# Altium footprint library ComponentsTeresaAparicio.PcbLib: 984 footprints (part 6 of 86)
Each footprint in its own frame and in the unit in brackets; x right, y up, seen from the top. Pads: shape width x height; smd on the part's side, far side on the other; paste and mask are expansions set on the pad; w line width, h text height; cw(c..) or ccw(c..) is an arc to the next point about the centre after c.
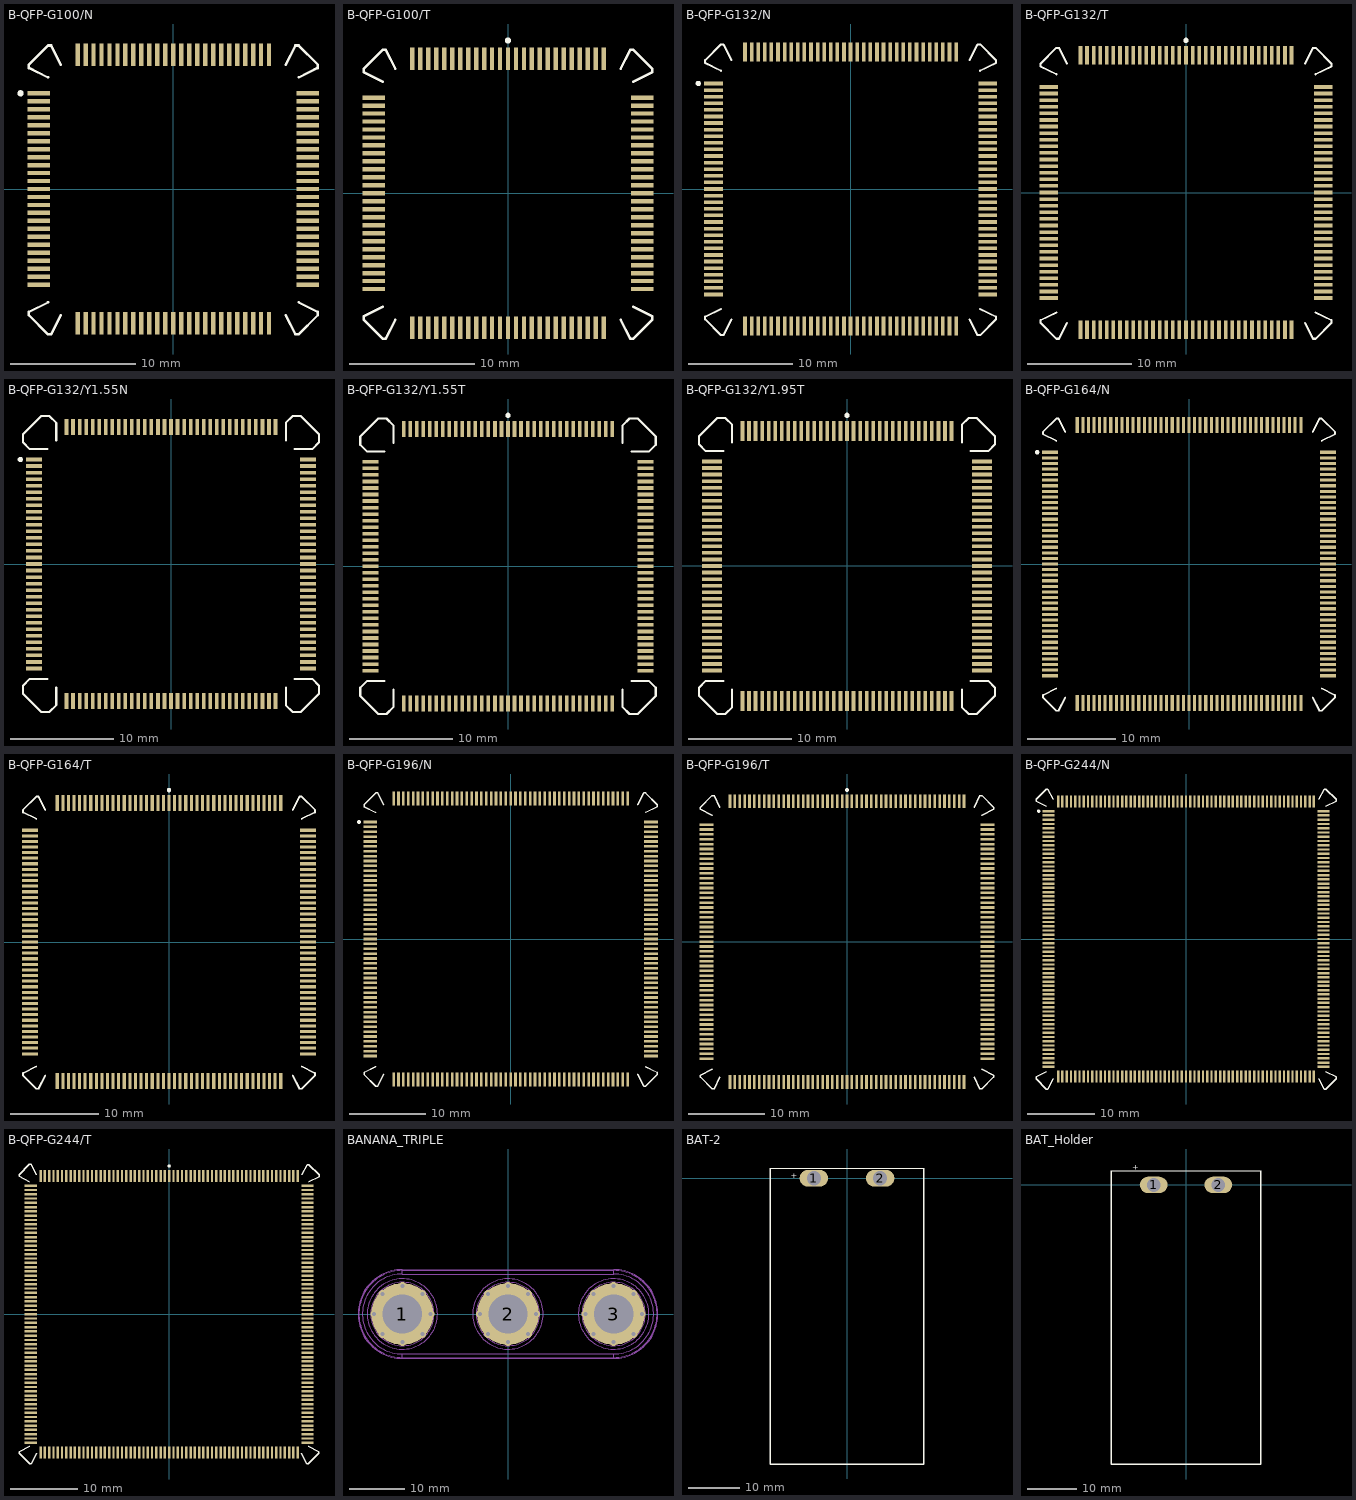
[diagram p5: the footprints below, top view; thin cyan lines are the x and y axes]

## B-QFP-G100/N [mm] "PQFP; 100 Leads; Body 19 x 19 mm; Pitch 0.635 mm"
height 4.57
pads (100):
  rect 1.8x0.35 smd: 1(-10.7,7.62) 2(-10.7,6.985) 3(-10.7,6.35) 4(-10.7,5.715) 5(-10.7,5.08) 6(-10.7,4.445) 7(-10.7,3.81) 8(-10.7,3.175) 9(-10.7,2.54) 10(-10.7,1.905) 11(-10.7,1.27) 12(-10.7,0.635) 13(-10.7,0) 14(-10.7,-0.635) 15(-10.7,-1.27) 16(-10.7,-1.905) 17(-10.7,-2.54) 18(-10.7,-3.175) 19(-10.7,-3.81) 20(-10.7,-4.445) 21(-10.7,-5.08) 22(-10.7,-5.715) 23(-10.7,-6.35) 24(-10.7,-6.985) 25(-10.7,-7.62) 51(10.7,-7.62) 52(10.7,-6.985) 53(10.7,-6.35) 54(10.7,-5.715) 55(10.7,-5.08) 56(10.7,-4.445) 57(10.7,-3.81) 58(10.7,-3.175) 59(10.7,-2.54) 60(10.7,-1.905) 61(10.7,-1.27) 62(10.7,-0.635) 63(10.7,0) 64(10.7,0.635) 65(10.7,1.27) 66(10.7,1.905) 67(10.7,2.54) 68(10.7,3.175) 69(10.7,3.81) 70(10.7,4.445) 71(10.7,5.08) 72(10.7,5.715) 73(10.7,6.35) 74(10.7,6.985) 75(10.7,7.62)
  rect 0.35x1.8 smd: 26(-7.62,-10.7) 27(-6.985,-10.7) 28(-6.35,-10.7) 29(-5.715,-10.7) 30(-5.08,-10.7) 31(-4.445,-10.7) 32(-3.81,-10.7) 33(-3.175,-10.7) 34(-2.54,-10.7) 35(-1.905,-10.7) 36(-1.27,-10.7) 37(-0.635,-10.7) 38(0,-10.7) 39(0.635,-10.7) 40(1.27,-10.7) 41(1.905,-10.7) 42(2.54,-10.7) 43(3.175,-10.7) 44(3.81,-10.7) 45(4.445,-10.7) 46(5.08,-10.7) 47(5.715,-10.7) 48(6.35,-10.7) 49(6.985,-10.7) 50(7.62,-10.7) 76(7.62,10.7) 77(6.985,10.7) 78(6.35,10.7) 79(5.715,10.7) 80(5.08,10.7) 81(4.445,10.7) 82(3.81,10.7) 83(3.175,10.7) 84(2.54,10.7) 85(1.905,10.7) 86(1.27,10.7) 87(0.635,10.7) 88(0,10.7) 89(-0.635,10.7) 90(-1.27,10.7) 91(-1.905,10.7) 92(-2.54,10.7) 93(-3.175,10.7) 94(-3.81,10.7) 95(-4.445,10.7) 96(-5.08,10.7) 97(-5.715,10.7) 98(-6.35,10.7) 99(-6.985,10.7) 100(-7.62,10.7)
Top Overlay:
  circle w0.25: c-12.16,7.62 r0.125
  lines w0.2: -11.5,-9.797 -9.976,-9.035 ; -11.5,-9.779 -11.5,-10.051 -9.976,-11.575 -9.722,-11.575 -8.96,-10.051 ; -11.5,9.629 -11.5,9.901 -9.976,11.425 -9.722,11.425 -8.96,9.901 ; -11.5,9.647 -9.976,8.885 ; 8.96,-10.051 9.722,-11.575 9.976,-11.575 11.5,-10.051 11.5,-9.779 ; 8.96,9.901 9.722,11.425 9.976,11.425 11.5,9.901 11.5,9.629 ; 9.976,-9.035 11.5,-9.797 ; 9.976,8.885 11.5,9.647

## B-QFP-G100/T [mm] "PQFP; 100 Leads; Body 19 x 19 mm; Pitch 0.635 mm"
height 4.57
pads (100):
  rect 0.35x1.8 smd: 1(0,10.7) 2(-0.635,10.7) 3(-1.27,10.7) 4(-1.905,10.7) 5(-2.54,10.7) 6(-3.175,10.7) 7(-3.81,10.7) 8(-4.445,10.7) 9(-5.08,10.7) 10(-5.715,10.7) 11(-6.35,10.7) 12(-6.985,10.7) 13(-7.62,10.7) 39(-7.62,-10.7) 40(-6.985,-10.7) 41(-6.35,-10.7) 42(-5.715,-10.7) 43(-5.08,-10.7) 44(-4.445,-10.7) 45(-3.81,-10.7) 46(-3.175,-10.7) 47(-2.54,-10.7) 48(-1.905,-10.7) 49(-1.27,-10.7) 50(-0.635,-10.7) 51(0,-10.7) 52(0.635,-10.7) 53(1.27,-10.7) 54(1.905,-10.7) 55(2.54,-10.7) 56(3.175,-10.7) 57(3.81,-10.7) 58(4.445,-10.7) 59(5.08,-10.7) 60(5.715,-10.7) 61(6.35,-10.7) 62(6.985,-10.7) 63(7.62,-10.7) 89(7.62,10.7) 90(6.985,10.7) 91(6.35,10.7) 92(5.715,10.7) 93(5.08,10.7) 94(4.445,10.7) 95(3.81,10.7) 96(3.175,10.7) 97(2.54,10.7) 98(1.905,10.7) 99(1.27,10.7) 100(0.635,10.7)
  rect 1.8x0.35 smd: 14(-10.7,7.62) 15(-10.7,6.985) 16(-10.7,6.35) 17(-10.7,5.715) 18(-10.7,5.08) 19(-10.7,4.445) 20(-10.7,3.81) 21(-10.7,3.175) 22(-10.7,2.54) 23(-10.7,1.905) 24(-10.7,1.27) 25(-10.7,0.635) 26(-10.7,0) 27(-10.7,-0.635) 28(-10.7,-1.27) 29(-10.7,-1.905) 30(-10.7,-2.54) 31(-10.7,-3.175) 32(-10.7,-3.81) 33(-10.7,-4.445) 34(-10.7,-5.08) 35(-10.7,-5.715) 36(-10.7,-6.35) 37(-10.7,-6.985) 38(-10.7,-7.62) 64(10.7,-7.62) 65(10.7,-6.985) 66(10.7,-6.35) 67(10.7,-5.715) 68(10.7,-5.08) 69(10.7,-4.445) 70(10.7,-3.81) 71(10.7,-3.175) 72(10.7,-2.54) 73(10.7,-1.905) 74(10.7,-1.27) 75(10.7,-0.635) 76(10.7,0) 77(10.7,0.635) 78(10.7,1.27) 79(10.7,1.905) 80(10.7,2.54) 81(10.7,3.175) 82(10.7,3.81) 83(10.7,4.445) 84(10.7,5.08) 85(10.7,5.715) 86(10.7,6.35) 87(10.7,6.985) 88(10.7,7.62)
Top Overlay:
  circle w0.25: c0,12.16 r0.125
  lines w0.2: -11.5,-9.797 -9.976,-9.035 ; -11.5,-9.779 -11.5,-10.051 -9.976,-11.575 -9.722,-11.575 -8.96,-10.051 ; -11.5,9.629 -11.5,9.901 -9.976,11.425 -9.722,11.425 -8.96,9.901 ; -11.5,9.647 -9.976,8.885 ; 8.96,-10.051 9.722,-11.575 9.976,-11.575 11.5,-10.051 11.5,-9.779 ; 8.96,9.901 9.722,11.425 9.976,11.425 11.5,9.901 11.5,9.629 ; 9.976,-9.035 11.5,-9.797 ; 9.976,8.885 11.5,9.647

## B-QFP-G132/N [mm] "PQFP; 132 Leads; Body 24 x 24 mm; Pitch 0.635 mm"
height 4.57
pads (132):
  rect 1.8x0.35 smd: 1(-13.2,10.16) 2(-13.2,9.525) 3(-13.2,8.89) 4(-13.2,8.255) 5(-13.2,7.62) 6(-13.2,6.985) 7(-13.2,6.35) 8(-13.2,5.715) 9(-13.2,5.08) 10(-13.2,4.445) 11(-13.2,3.81) 12(-13.2,3.175) 13(-13.2,2.54) 14(-13.2,1.905) 15(-13.2,1.27) 16(-13.2,0.635) 17(-13.2,0) 18(-13.2,-0.635) 19(-13.2,-1.27) 20(-13.2,-1.905) 21(-13.2,-2.54) 22(-13.2,-3.175) 23(-13.2,-3.81) 24(-13.2,-4.445) 25(-13.2,-5.08) 26(-13.2,-5.715) 27(-13.2,-6.35) 28(-13.2,-6.985) 29(-13.2,-7.62) 30(-13.2,-8.255) 31(-13.2,-8.89) 32(-13.2,-9.525) 33(-13.2,-10.16) 67(13.2,-10.16) 68(13.2,-9.525) 69(13.2,-8.89) 70(13.2,-8.255) 71(13.2,-7.62) 72(13.2,-6.985) 73(13.2,-6.35) 74(13.2,-5.715) 75(13.2,-5.08) 76(13.2,-4.445) 77(13.2,-3.81) 78(13.2,-3.175) 79(13.2,-2.54) 80(13.2,-1.905) 81(13.2,-1.27) 82(13.2,-0.635) 83(13.2,0) 84(13.2,0.635) 85(13.2,1.27) 86(13.2,1.905) 87(13.2,2.54) 88(13.2,3.175) 89(13.2,3.81) 90(13.2,4.445) 91(13.2,5.08) 92(13.2,5.715) 93(13.2,6.35) 94(13.2,6.985) 95(13.2,7.62) 96(13.2,8.255) 97(13.2,8.89) 98(13.2,9.525) 99(13.2,10.16)
  rect 0.35x1.8 smd: 34(-10.16,-13.2) 35(-9.525,-13.2) 36(-8.89,-13.2) 37(-8.255,-13.2) 38(-7.62,-13.2) 39(-6.985,-13.2) 40(-6.35,-13.2) 41(-5.715,-13.2) 42(-5.08,-13.2) 43(-4.445,-13.2) 44(-3.81,-13.2) 45(-3.175,-13.2) 46(-2.54,-13.2) 47(-1.905,-13.2) 48(-1.27,-13.2) 49(-0.635,-13.2) 50(0,-13.2) 51(0.635,-13.2) 52(1.27,-13.2) 53(1.905,-13.2) 54(2.54,-13.2) 55(3.175,-13.2) 56(3.81,-13.2) 57(4.445,-13.2) 58(5.08,-13.2) 59(5.715,-13.2) 60(6.35,-13.2) 61(6.985,-13.2) 62(7.62,-13.2) 63(8.255,-13.2) 64(8.89,-13.2) 65(9.525,-13.2) 66(10.16,-13.2) 100(10.16,13.2) 101(9.525,13.2) 102(8.89,13.2) 103(8.255,13.2) 104(7.62,13.2) 105(6.985,13.2) 106(6.35,13.2) 107(5.715,13.2) 108(5.08,13.2) 109(4.445,13.2) 110(3.81,13.2) 111(3.175,13.2) 112(2.54,13.2) 113(1.905,13.2) 114(1.27,13.2) 115(0.635,13.2) 116(0,13.2) 117(-0.635,13.2) 118(-1.27,13.2) 119(-1.905,13.2) 120(-2.54,13.2) 121(-3.175,13.2) 122(-3.81,13.2) 123(-4.445,13.2) 124(-5.08,13.2) 125(-5.715,13.2) 126(-6.35,13.2) 127(-6.985,13.2) 128(-7.62,13.2) 129(-8.255,13.2) 130(-8.89,13.2) 131(-9.525,13.2) 132(-10.16,13.2)
Top Overlay:
  circle w0.25: c-14.66,10.16 r0.125
  lines w0.2: -14,-12.297 -12.476,-11.535 ; -14,-12.279 -14,-12.551 -12.476,-14.075 -12.222,-14.075 -11.46,-12.551 ; -14,12.129 -14,12.401 -12.476,13.925 -12.222,13.925 -11.46,12.401 ; -14,12.147 -12.476,11.385 ; 11.46,-12.551 12.222,-14.075 12.476,-14.075 14,-12.551 14,-12.279 ; 11.46,12.401 12.222,13.925 12.476,13.925 14,12.401 14,12.129 ; 12.476,-11.535 14,-12.297 ; 12.476,11.385 14,12.147

## B-QFP-G132/T [mm] "PQFP; 132 Leads; Body 24 x 24 mm; Pitch 0.635 mm"
height 4.57
pads (132):
  rect 0.35x1.8 smd: 1(0,13.2) 2(-0.635,13.2) 3(-1.27,13.2) 4(-1.905,13.2) 5(-2.54,13.2) 6(-3.175,13.2) 7(-3.81,13.2) 8(-4.445,13.2) 9(-5.08,13.2) 10(-5.715,13.2) 11(-6.35,13.2) 12(-6.985,13.2) 13(-7.62,13.2) 14(-8.255,13.2) 15(-8.89,13.2) 16(-9.525,13.2) 17(-10.16,13.2) 51(-10.16,-13.2) 52(-9.525,-13.2) 53(-8.89,-13.2) 54(-8.255,-13.2) 55(-7.62,-13.2) 56(-6.985,-13.2) 57(-6.35,-13.2) 58(-5.715,-13.2) 59(-5.08,-13.2) 60(-4.445,-13.2) 61(-3.81,-13.2) 62(-3.175,-13.2) 63(-2.54,-13.2) 64(-1.905,-13.2) 65(-1.27,-13.2) 66(-0.635,-13.2) 67(0,-13.2) 68(0.635,-13.2) 69(1.27,-13.2) 70(1.905,-13.2) 71(2.54,-13.2) 72(3.175,-13.2) 73(3.81,-13.2) 74(4.445,-13.2) 75(5.08,-13.2) 76(5.715,-13.2) 77(6.35,-13.2) 78(6.985,-13.2) 79(7.62,-13.2) 80(8.255,-13.2) 81(8.89,-13.2) 82(9.525,-13.2) 83(10.16,-13.2) 117(10.16,13.2) 118(9.525,13.2) 119(8.89,13.2) 120(8.255,13.2) 121(7.62,13.2) 122(6.985,13.2) 123(6.35,13.2) 124(5.715,13.2) 125(5.08,13.2) 126(4.445,13.2) 127(3.81,13.2) 128(3.175,13.2) 129(2.54,13.2) 130(1.905,13.2) 131(1.27,13.2) 132(0.635,13.2)
  rect 1.8x0.35 smd: 18(-13.2,10.16) 19(-13.2,9.525) 20(-13.2,8.89) 21(-13.2,8.255) 22(-13.2,7.62) 23(-13.2,6.985) 24(-13.2,6.35) 25(-13.2,5.715) 26(-13.2,5.08) 27(-13.2,4.445) 28(-13.2,3.81) 29(-13.2,3.175) 30(-13.2,2.54) 31(-13.2,1.905) 32(-13.2,1.27) 33(-13.2,0.635) 34(-13.2,0) 35(-13.2,-0.635) 36(-13.2,-1.27) 37(-13.2,-1.905) 38(-13.2,-2.54) 39(-13.2,-3.175) 40(-13.2,-3.81) 41(-13.2,-4.445) 42(-13.2,-5.08) 43(-13.2,-5.715) 44(-13.2,-6.35) 45(-13.2,-6.985) 46(-13.2,-7.62) 47(-13.2,-8.255) 48(-13.2,-8.89) 49(-13.2,-9.525) 50(-13.2,-10.16) 84(13.2,-10.16) 85(13.2,-9.525) 86(13.2,-8.89) 87(13.2,-8.255) 88(13.2,-7.62) 89(13.2,-6.985) 90(13.2,-6.35) 91(13.2,-5.715) 92(13.2,-5.08) 93(13.2,-4.445) 94(13.2,-3.81) 95(13.2,-3.175) 96(13.2,-2.54) 97(13.2,-1.905) 98(13.2,-1.27) 99(13.2,-0.635) 100(13.2,0) 101(13.2,0.635) 102(13.2,1.27) 103(13.2,1.905) 104(13.2,2.54) 105(13.2,3.175) 106(13.2,3.81) 107(13.2,4.445) 108(13.2,5.08) 109(13.2,5.715) 110(13.2,6.35) 111(13.2,6.985) 112(13.2,7.62) 113(13.2,8.255) 114(13.2,8.89) 115(13.2,9.525) 116(13.2,10.16)
Top Overlay:
  circle w0.25: c0,14.65 r0.125
  lines w0.2: -14,-12.297 -12.476,-11.535 ; -14,-12.279 -14,-12.551 -12.476,-14.075 -12.222,-14.075 -11.46,-12.551 ; -14,12.129 -14,12.401 -12.476,13.925 -12.222,13.925 -11.46,12.401 ; -14,12.147 -12.476,11.385 ; 11.46,-12.551 12.222,-14.075 12.476,-14.075 14,-12.551 14,-12.279 ; 11.46,12.401 12.222,13.925 12.476,13.925 14,12.401 14,12.129 ; 12.476,-11.535 14,-12.297 ; 12.476,11.385 14,12.147

## B-QFP-G132/Y1.55N [mm] "132-Pin Plastic Quad Flat Pack (PQFP132)"
height 4.57
pads (132):
  rect 1.55x0.35 smd: 1(-13.33,10.16) 2(-13.33,9.525) 3(-13.33,8.89) 4(-13.33,8.255) 5(-13.33,7.62) 6(-13.33,6.985) 7(-13.33,6.35) 8(-13.33,5.715) 9(-13.33,5.08) 10(-13.33,4.445) 11(-13.33,3.81) 12(-13.33,3.175) 13(-13.33,2.54) 14(-13.33,1.905) 15(-13.33,1.27) 16(-13.33,0.635) 17(-13.33,0) 18(-13.33,-0.635) 19(-13.33,-1.27) 20(-13.33,-1.905) 21(-13.33,-2.54) 22(-13.33,-3.175) 23(-13.33,-3.81) 24(-13.33,-4.445) 25(-13.33,-5.08) 26(-13.33,-5.715) 27(-13.33,-6.35) 28(-13.33,-6.985) 29(-13.33,-7.62) 30(-13.33,-8.255) 31(-13.33,-8.89) 32(-13.33,-9.525) 33(-13.33,-10.16) 67(13.33,-10.16) 68(13.33,-9.525) 69(13.33,-8.89) 70(13.33,-8.255) 71(13.33,-7.62) 72(13.33,-6.985) 73(13.33,-6.35) 74(13.33,-5.715) 75(13.33,-5.08) 76(13.33,-4.445) 77(13.33,-3.81) 78(13.33,-3.175) 79(13.33,-2.54) 80(13.33,-1.905) 81(13.33,-1.27) 82(13.33,-0.635) 83(13.33,0) 84(13.33,0.635) 85(13.33,1.27) 86(13.33,1.905) 87(13.33,2.54) 88(13.33,3.175) 89(13.33,3.81) 90(13.33,4.445) 91(13.33,5.08) 92(13.33,5.715) 93(13.33,6.35) 94(13.33,6.985) 95(13.33,7.62) 96(13.33,8.255) 97(13.33,8.89) 98(13.33,9.525) 99(13.33,10.16)
  rect 0.35x1.55 smd: 34(-10.16,-13.33) 35(-9.525,-13.33) 36(-8.89,-13.33) 37(-8.255,-13.33) 38(-7.62,-13.33) 39(-6.985,-13.33) 40(-6.35,-13.33) 41(-5.715,-13.33) 42(-5.08,-13.33) 43(-4.445,-13.33) 44(-3.81,-13.33) 45(-3.175,-13.33) 46(-2.54,-13.33) 47(-1.905,-13.33) 48(-1.27,-13.33) 49(-0.635,-13.33) 50(0,-13.33) 51(0.635,-13.33) 52(1.27,-13.33) 53(1.905,-13.33) 54(2.54,-13.33) 55(3.175,-13.33) 56(3.81,-13.33) 57(4.445,-13.33) 58(5.08,-13.33) 59(5.715,-13.33) 60(6.35,-13.33) 61(6.985,-13.33) 62(7.62,-13.33) 63(8.255,-13.33) 64(8.89,-13.33) 65(9.525,-13.33) 66(10.16,-13.33) 100(10.16,13.33) 101(9.525,13.33) 102(8.89,13.33) 103(8.255,13.33) 104(7.62,13.33) 105(6.985,13.33) 106(6.35,13.33) 107(5.715,13.33) 108(5.08,13.33) 109(4.445,13.33) 110(3.81,13.33) 111(3.175,13.33) 112(2.54,13.33) 113(1.905,13.33) 114(1.27,13.33) 115(0.635,13.33) 116(0,13.33) 117(-0.635,13.33) 118(-1.27,13.33) 119(-1.905,13.33) 120(-2.54,13.33) 121(-3.175,13.33) 122(-3.81,13.33) 123(-4.445,13.33) 124(-5.08,13.33) 125(-5.715,13.33) 126(-6.35,13.33) 127(-6.985,13.33) 128(-7.62,13.33) 129(-8.255,13.33) 130(-8.89,13.33) 131(-9.525,13.33) 132(-10.16,13.33)
Top Overlay:
  circle w0.25: c-14.655,10.16 r0.125
  lines w0.2: -12.02,-11.16 -13.717,-11.16 -14.387,-11.83 -14.387,-12.63 -12.63,-14.387 -11.83,-14.387 -11.16,-13.717 -11.16,-12.02 ; -12.02,11.16 -13.718,11.16 -14.387,11.83 -14.387,12.63 -12.63,14.388 -11.83,14.388 -11.16,13.718 -11.16,12.02 ; 11.16,-12.02 11.16,-13.717 11.83,-14.387 12.63,-14.387 14.387,-12.63 14.387,-11.83 13.718,-11.16 12.02,-11.16 ; 11.16,12.02 11.16,13.718 11.83,14.388 12.63,14.388 14.387,12.63 14.387,11.83 13.717,11.16 12.02,11.16

## B-QFP-G132/Y1.55T [mm] "Bumpered PQFP; 132 Leads; Pitch 0.635 mm;"
height 5.59
pads (132):
  rect 0.35x1.55 smd: 1(0,13.375) 2(-0.635,13.375) 3(-1.27,13.375) 4(-1.905,13.375) 5(-2.54,13.375) 6(-3.175,13.375) 7(-3.81,13.375) 8(-4.445,13.375) 9(-5.08,13.375) 10(-5.715,13.375) 11(-6.35,13.375) 12(-6.985,13.375) 13(-7.62,13.375) 14(-8.255,13.375) 15(-8.89,13.375) 16(-9.525,13.375) 17(-10.16,13.375) 51(-10.16,-13.375) 52(-9.525,-13.375) 53(-8.89,-13.375) 54(-8.255,-13.375) 55(-7.62,-13.375) 56(-6.985,-13.375) 57(-6.35,-13.375) 58(-5.715,-13.375) 59(-5.08,-13.375) 60(-4.445,-13.375) 61(-3.81,-13.375) 62(-3.175,-13.375) 63(-2.54,-13.375) 64(-1.905,-13.375) 65(-1.27,-13.375) 66(-0.635,-13.375) 67(0,-13.375) 68(0.635,-13.375) 69(1.27,-13.375) 70(1.905,-13.375) 71(2.54,-13.375) 72(3.175,-13.375) 73(3.81,-13.375) 74(4.445,-13.375) 75(5.08,-13.375) 76(5.715,-13.375) 77(6.35,-13.375) 78(6.985,-13.375) 79(7.62,-13.375) 80(8.255,-13.375) 81(8.89,-13.375) 82(9.525,-13.375) 83(10.16,-13.375) 117(10.16,13.375) 118(9.525,13.375) 119(8.89,13.375) 120(8.255,13.375) 121(7.62,13.375) 122(6.985,13.375) 123(6.35,13.375) 124(5.715,13.375) 125(5.08,13.375) 126(4.445,13.375) 127(3.81,13.375) 128(3.175,13.375) 129(2.54,13.375) 130(1.905,13.375) 131(1.27,13.375) 132(0.635,13.375)
  rect 1.55x0.35 smd: 18(-13.375,10.16) 19(-13.375,9.525) 20(-13.375,8.89) 21(-13.375,8.255) 22(-13.375,7.62) 23(-13.375,6.985) 24(-13.375,6.35) 25(-13.375,5.715) 26(-13.375,5.08) 27(-13.375,4.445) 28(-13.375,3.81) 29(-13.375,3.175) 30(-13.375,2.54) 31(-13.375,1.905) 32(-13.375,1.27) 33(-13.375,0.635) 34(-13.375,0) 35(-13.375,-0.635) 36(-13.375,-1.27) 37(-13.375,-1.905) 38(-13.375,-2.54) 39(-13.375,-3.175) 40(-13.375,-3.81) 41(-13.375,-4.445) 42(-13.375,-5.08) 43(-13.375,-5.715) 44(-13.375,-6.35) 45(-13.375,-6.985) 46(-13.375,-7.62) 47(-13.375,-8.255) 48(-13.375,-8.89) 49(-13.375,-9.525) 50(-13.375,-10.16) 84(13.375,-10.16) 85(13.375,-9.525) 86(13.375,-8.89) 87(13.375,-8.255) 88(13.375,-7.62) 89(13.375,-6.985) 90(13.375,-6.35) 91(13.375,-5.715) 92(13.375,-5.08) 93(13.375,-4.445) 94(13.375,-3.81) 95(13.375,-3.175) 96(13.375,-2.54) 97(13.375,-1.905) 98(13.375,-1.27) 99(13.375,-0.635) 100(13.375,0) 101(13.375,0.635) 102(13.375,1.27) 103(13.375,1.905) 104(13.375,2.54) 105(13.375,3.175) 106(13.375,3.81) 107(13.375,4.445) 108(13.375,5.08) 109(13.375,5.715) 110(13.375,6.35) 111(13.375,6.985) 112(13.375,7.62) 113(13.375,8.255) 114(13.375,8.89) 115(13.375,9.525) 116(13.375,10.16)
Top Overlay:
  circle w0.25: c0,14.7 r0.125
  lines w0.2: -12.02,-11.16 -13.717,-11.16 -14.387,-11.83 -14.387,-12.63 -12.63,-14.387 -11.83,-14.387 -11.16,-13.717 -11.16,-12.02 ; -12.02,11.16 -13.718,11.16 -14.387,11.83 -14.387,12.63 -12.63,14.388 -11.83,14.388 -11.16,13.718 -11.16,12.02 ; 11.16,-12.02 11.16,-13.717 11.83,-14.387 12.63,-14.387 14.387,-12.63 14.387,-11.83 13.718,-11.16 12.02,-11.16 ; 11.16,12.02 11.16,13.718 11.83,14.388 12.63,14.388 14.387,12.63 14.387,11.83 13.717,11.16 12.02,11.16

## B-QFP-G132/Y1.95T [mm] "PQFP; 132 Leads; Body 24 x 24 mm; Pitch 0.635 mm"
height 4.57
pads (132):
  rect 0.35x1.95 smd: 1(0,13.125) 2(-0.635,13.125) 3(-1.27,13.125) 4(-1.905,13.125) 5(-2.54,13.125) 6(-3.175,13.125) 7(-3.81,13.125) 8(-4.445,13.125) 9(-5.08,13.125) 10(-5.715,13.125) 11(-6.35,13.125) 12(-6.985,13.125) 13(-7.62,13.125) 14(-8.255,13.125) 15(-8.89,13.125) 16(-9.525,13.125) 17(-10.16,13.125) 51(-10.16,-13.125) 52(-9.525,-13.125) 53(-8.89,-13.125) 54(-8.255,-13.125) 55(-7.62,-13.125) 56(-6.985,-13.125) 57(-6.35,-13.125) 58(-5.715,-13.125) 59(-5.08,-13.125) 60(-4.445,-13.125) 61(-3.81,-13.125) 62(-3.175,-13.125) 63(-2.54,-13.125) 64(-1.905,-13.125) 65(-1.27,-13.125) 66(-0.635,-13.125) 67(0,-13.125) 68(0.635,-13.125) 69(1.27,-13.125) 70(1.905,-13.125) 71(2.54,-13.125) 72(3.175,-13.125) 73(3.81,-13.125) 74(4.445,-13.125) 75(5.08,-13.125) 76(5.715,-13.125) 77(6.35,-13.125) 78(6.985,-13.125) 79(7.62,-13.125) 80(8.255,-13.125) 81(8.89,-13.125) 82(9.525,-13.125) 83(10.16,-13.125) 117(10.16,13.125) 118(9.525,13.125) 119(8.89,13.125) 120(8.255,13.125) 121(7.62,13.125) 122(6.985,13.125) 123(6.35,13.125) 124(5.715,13.125) 125(5.08,13.125) 126(4.445,13.125) 127(3.81,13.125) 128(3.175,13.125) 129(2.54,13.125) 130(1.905,13.125) 131(1.27,13.125) 132(0.635,13.125)
  rect 1.95x0.35 smd: 18(-13.125,10.16) 19(-13.125,9.525) 20(-13.125,8.89) 21(-13.125,8.255) 22(-13.125,7.62) 23(-13.125,6.985) 24(-13.125,6.35) 25(-13.125,5.715) 26(-13.125,5.08) 27(-13.125,4.445) 28(-13.125,3.81) 29(-13.125,3.175) 30(-13.125,2.54) 31(-13.125,1.905) 32(-13.125,1.27) 33(-13.125,0.635) 34(-13.125,0) 35(-13.125,-0.635) 36(-13.125,-1.27) 37(-13.125,-1.905) 38(-13.125,-2.54) 39(-13.125,-3.175) 40(-13.125,-3.81) 41(-13.125,-4.445) 42(-13.125,-5.08) 43(-13.125,-5.715) 44(-13.125,-6.35) 45(-13.125,-6.985) 46(-13.125,-7.62) 47(-13.125,-8.255) 48(-13.125,-8.89) 49(-13.125,-9.525) 50(-13.125,-10.16) 84(13.125,-10.16) 85(13.125,-9.525) 86(13.125,-8.89) 87(13.125,-8.255) 88(13.125,-7.62) 89(13.125,-6.985) 90(13.125,-6.35) 91(13.125,-5.715) 92(13.125,-5.08) 93(13.125,-4.445) 94(13.125,-3.81) 95(13.125,-3.175) 96(13.125,-2.54) 97(13.125,-1.905) 98(13.125,-1.27) 99(13.125,-0.635) 100(13.125,0) 101(13.125,0.635) 102(13.125,1.27) 103(13.125,1.905) 104(13.125,2.54) 105(13.125,3.175) 106(13.125,3.81) 107(13.125,4.445) 108(13.125,5.08) 109(13.125,5.715) 110(13.125,6.35) 111(13.125,6.985) 112(13.125,7.62) 113(13.125,8.255) 114(13.125,8.89) 115(13.125,9.525) 116(13.125,10.16)
Top Overlay:
  circle w0.25: c0,14.65 r0.125
  lines w0.2: -12.02,-11.16 -13.718,-11.16 -14.388,-11.83 -14.388,-12.63 -12.63,-14.387 -11.83,-14.387 -11.16,-13.717 -11.16,-12.02 ; -12.02,11.16 -13.718,11.16 -14.388,11.83 -14.388,12.63 -12.63,14.388 -11.83,14.388 -11.16,13.718 -11.16,12.02 ; 11.16,-12.02 11.16,-13.717 11.83,-14.387 12.63,-14.387 14.387,-12.63 14.387,-11.83 13.717,-11.16 12.02,-11.16 ; 11.16,12.02 11.16,13.718 11.83,14.388 12.63,14.388 14.387,12.63 14.387,11.83 13.717,11.16 12.02,11.16

## B-QFP-G164/N [mm] "PQFP; 164 Leads; Body 29 x 29 mm; Pitch 0.635 mm"
height 4.75
pads (164):
  rect 1.8x0.35 smd: 1(-15.8,12.7) 2(-15.8,12.065) 3(-15.8,11.43) 4(-15.8,10.795) 5(-15.8,10.16) 6(-15.8,9.525) 7(-15.8,8.89) 8(-15.8,8.255) 9(-15.8,7.62) 10(-15.8,6.985) 11(-15.8,6.35) 12(-15.8,5.715) 13(-15.8,5.08) 14(-15.8,4.445) 15(-15.8,3.81) 16(-15.8,3.175) 17(-15.8,2.54) 18(-15.8,1.905) 19(-15.8,1.27) 20(-15.8,0.635) 21(-15.8,0) 22(-15.8,-0.635) 23(-15.8,-1.27) 24(-15.8,-1.905) 25(-15.8,-2.54) 26(-15.8,-3.175) 27(-15.8,-3.81) 28(-15.8,-4.445) 29(-15.8,-5.08) 30(-15.8,-5.715) 31(-15.8,-6.35) 32(-15.8,-6.985) 33(-15.8,-7.62) 34(-15.8,-8.255) 35(-15.8,-8.89) 36(-15.8,-9.525) 37(-15.8,-10.16) 38(-15.8,-10.795) 39(-15.8,-11.43) 40(-15.8,-12.065) 41(-15.8,-12.7) 83(15.8,-12.7) 84(15.8,-12.065) 85(15.8,-11.43) 86(15.8,-10.795) 87(15.8,-10.16) 88(15.8,-9.525) 89(15.8,-8.89) 90(15.8,-8.255) 91(15.8,-7.62) 92(15.8,-6.985) 93(15.8,-6.35) 94(15.8,-5.715) 95(15.8,-5.08) 96(15.8,-4.445) 97(15.8,-3.81) 98(15.8,-3.175) 99(15.8,-2.54) 100(15.8,-1.905) 101(15.8,-1.27) 102(15.8,-0.635) 103(15.8,0) 104(15.8,0.635) 105(15.8,1.27) 106(15.8,1.905) 107(15.8,2.54) 108(15.8,3.175) 109(15.8,3.81) 110(15.8,4.445) 111(15.8,5.08) 112(15.8,5.715) 113(15.8,6.35) 114(15.8,6.985) 115(15.8,7.62) 116(15.8,8.255) 117(15.8,8.89) 118(15.8,9.525) 119(15.8,10.16) 120(15.8,10.795) 121(15.8,11.43) 122(15.8,12.065) 123(15.8,12.7)
  rect 0.35x1.8 smd: 42(-12.7,-15.8) 43(-12.065,-15.8) 44(-11.43,-15.8) 45(-10.795,-15.8) 46(-10.16,-15.8) 47(-9.525,-15.8) 48(-8.89,-15.8) 49(-8.255,-15.8) 50(-7.62,-15.8) 51(-6.985,-15.8) 52(-6.35,-15.8) 53(-5.715,-15.8) 54(-5.08,-15.8) 55(-4.445,-15.8) 56(-3.81,-15.8) 57(-3.175,-15.8) 58(-2.54,-15.8) 59(-1.905,-15.8) 60(-1.27,-15.8) 61(-0.635,-15.8) 62(0,-15.8) 63(0.635,-15.8) 64(1.27,-15.8) 65(1.905,-15.8) 66(2.54,-15.8) 67(3.175,-15.8) 68(3.81,-15.8) 69(4.445,-15.8) 70(5.08,-15.8) 71(5.715,-15.8) 72(6.35,-15.8) 73(6.985,-15.8) 74(7.62,-15.8) 75(8.255,-15.8) 76(8.89,-15.8) 77(9.525,-15.8) 78(10.16,-15.8) 79(10.795,-15.8) 80(11.43,-15.8) 81(12.065,-15.8) 82(12.7,-15.8) 124(12.7,15.8) 125(12.065,15.8) 126(11.43,15.8) 127(10.795,15.8) 128(10.16,15.8) 129(9.525,15.8) 130(8.89,15.8) 131(8.255,15.8) 132(7.62,15.8) 133(6.985,15.8) 134(6.35,15.8) 135(5.715,15.8) 136(5.08,15.8) 137(4.445,15.8) 138(3.81,15.8) 139(3.175,15.8) 140(2.54,15.8) 141(1.905,15.8) 142(1.27,15.8) 143(0.635,15.8) 144(0,15.8) 145(-0.635,15.8) 146(-1.27,15.8) 147(-1.905,15.8) 148(-2.54,15.8) 149(-3.175,15.8) 150(-3.81,15.8) 151(-4.445,15.8) 152(-5.08,15.8) 153(-5.715,15.8) 154(-6.35,15.8) 155(-6.985,15.8) 156(-7.62,15.8) 157(-8.255,15.8) 158(-8.89,15.8) 159(-9.525,15.8) 160(-10.16,15.8) 161(-10.795,15.8) 162(-11.43,15.8) 163(-12.065,15.8) 164(-12.7,15.8)
Top Overlay:
  circle w0.25: c-17.26,12.7 r0.125
  lines w0.2: -16.6,-14.897 -15.076,-14.135 ; -16.6,-14.879 -16.6,-15.151 -15.076,-16.675 -14.822,-16.675 -14.06,-15.151 ; -16.6,14.729 -16.6,15.001 -15.076,16.525 -14.822,16.525 -14.06,15.001 ; -16.6,14.747 -15.076,13.985 ; 14.06,-15.151 14.822,-16.675 15.076,-16.675 16.6,-15.151 16.6,-14.879 ; 14.06,15.001 14.822,16.525 15.076,16.525 16.6,15.001 16.6,14.729 ; 15.076,-14.135 16.6,-14.897 ; 15.076,13.985 16.6,14.747

## B-QFP-G164/T [mm] "PQFP; 164 Leads; Body 29 x 29 mm; Pitch 0.635 mm"
height 4.75
pads (164):
  rect 0.35x1.8 smd: 1(0,15.8) 2(-0.635,15.8) 3(-1.27,15.8) 4(-1.905,15.8) 5(-2.54,15.8) 6(-3.175,15.8) 7(-3.81,15.8) 8(-4.445,15.8) 9(-5.08,15.8) 10(-5.715,15.8) 11(-6.35,15.8) 12(-6.985,15.8) 13(-7.62,15.8) 14(-8.255,15.8) 15(-8.89,15.8) 16(-9.525,15.8) 17(-10.16,15.8) 18(-10.795,15.8) 19(-11.43,15.8) 20(-12.065,15.8) 21(-12.7,15.8) 63(-12.7,-15.8) 64(-12.065,-15.8) 65(-11.43,-15.8) 66(-10.795,-15.8) 67(-10.16,-15.8) 68(-9.525,-15.8) 69(-8.89,-15.8) 70(-8.255,-15.8) 71(-7.62,-15.8) 72(-6.985,-15.8) 73(-6.35,-15.8) 74(-5.715,-15.8) 75(-5.08,-15.8) 76(-4.445,-15.8) 77(-3.81,-15.8) 78(-3.175,-15.8) 79(-2.54,-15.8) 80(-1.905,-15.8) 81(-1.27,-15.8) 82(-0.635,-15.8) 83(0,-15.8) 84(0.635,-15.8) 85(1.27,-15.8) 86(1.905,-15.8) 87(2.54,-15.8) 88(3.175,-15.8) 89(3.81,-15.8) 90(4.445,-15.8) 91(5.08,-15.8) 92(5.715,-15.8) 93(6.35,-15.8) 94(6.985,-15.8) 95(7.62,-15.8) 96(8.255,-15.8) 97(8.89,-15.8) 98(9.525,-15.8) 99(10.16,-15.8) 100(10.795,-15.8) 101(11.43,-15.8) 102(12.065,-15.8) 103(12.7,-15.8) 145(12.7,15.8) 146(12.065,15.8) 147(11.43,15.8) 148(10.795,15.8) 149(10.16,15.8) 150(9.525,15.8) 151(8.89,15.8) 152(8.255,15.8) 153(7.62,15.8) 154(6.985,15.8) 155(6.35,15.8) 156(5.715,15.8) 157(5.08,15.8) 158(4.445,15.8) 159(3.81,15.8) 160(3.175,15.8) 161(2.54,15.8) 162(1.905,15.8) 163(1.27,15.8) 164(0.635,15.8)
  rect 1.8x0.35 smd: 22(-15.8,12.7) 23(-15.8,12.065) 24(-15.8,11.43) 25(-15.8,10.795) 26(-15.8,10.16) 27(-15.8,9.525) 28(-15.8,8.89) 29(-15.8,8.255) 30(-15.8,7.62) 31(-15.8,6.985) 32(-15.8,6.35) 33(-15.8,5.715) 34(-15.8,5.08) 35(-15.8,4.445) 36(-15.8,3.81) 37(-15.8,3.175) 38(-15.8,2.54) 39(-15.8,1.905) 40(-15.8,1.27) 41(-15.8,0.635) 42(-15.8,0) 43(-15.8,-0.635) 44(-15.8,-1.27) 45(-15.8,-1.905) 46(-15.8,-2.54) 47(-15.8,-3.175) 48(-15.8,-3.81) 49(-15.8,-4.445) 50(-15.8,-5.08) 51(-15.8,-5.715) 52(-15.8,-6.35) 53(-15.8,-6.985) 54(-15.8,-7.62) 55(-15.8,-8.255) 56(-15.8,-8.89) 57(-15.8,-9.525) 58(-15.8,-10.16) 59(-15.8,-10.795) 60(-15.8,-11.43) 61(-15.8,-12.065) 62(-15.8,-12.7) 104(15.8,-12.7) 105(15.8,-12.065) 106(15.8,-11.43) 107(15.8,-10.795) 108(15.8,-10.16) 109(15.8,-9.525) 110(15.8,-8.89) 111(15.8,-8.255) 112(15.8,-7.62) 113(15.8,-6.985) 114(15.8,-6.35) 115(15.8,-5.715) 116(15.8,-5.08) 117(15.8,-4.445) 118(15.8,-3.81) 119(15.8,-3.175) 120(15.8,-2.54) 121(15.8,-1.905) 122(15.8,-1.27) 123(15.8,-0.635) 124(15.8,0) 125(15.8,0.635) 126(15.8,1.27) 127(15.8,1.905) 128(15.8,2.54) 129(15.8,3.175) 130(15.8,3.81) 131(15.8,4.445) 132(15.8,5.08) 133(15.8,5.715) 134(15.8,6.35) 135(15.8,6.985) 136(15.8,7.62) 137(15.8,8.255) 138(15.8,8.89) 139(15.8,9.525) 140(15.8,10.16) 141(15.8,10.795) 142(15.8,11.43) 143(15.8,12.065) 144(15.8,12.7)
Top Overlay:
  circle w0.25: c0,17.26 r0.125
  lines w0.2: -16.6,-14.897 -15.076,-14.135 ; -16.6,-14.879 -16.6,-15.151 -15.076,-16.675 -14.822,-16.675 -14.06,-15.151 ; -16.6,14.729 -16.6,15.001 -15.076,16.525 -14.822,16.525 -14.06,15.001 ; -16.6,14.747 -15.076,13.985 ; 14.06,-15.151 14.822,-16.675 15.076,-16.675 16.6,-15.151 16.6,-14.879 ; 14.06,15.001 14.822,16.525 15.076,16.525 16.6,15.001 16.6,14.729 ; 15.076,-14.135 16.6,-14.897 ; 15.076,13.985 16.6,14.747

## B-QFP-G196/N [mm] "PQFP; 196 Leads; Body 34 x 34 mm; Pitch 0.635 mm"
height 4.57
pads (196):
  rect 1.8x0.35 smd: 1(-18.3,15.24) 2(-18.3,14.605) 3(-18.3,13.97) 4(-18.3,13.335) 5(-18.3,12.7) 6(-18.3,12.065) 7(-18.3,11.43) 8(-18.3,10.795) 9(-18.3,10.16) 10(-18.3,9.525) 11(-18.3,8.89) 12(-18.3,8.255) 13(-18.3,7.62) 14(-18.3,6.985) 15(-18.3,6.35) 16(-18.3,5.715) 17(-18.3,5.08) 18(-18.3,4.445) 19(-18.3,3.81) 20(-18.3,3.175) 21(-18.3,2.54) 22(-18.3,1.905) 23(-18.3,1.27) 24(-18.3,0.635) 25(-18.3,0) 26(-18.3,-0.635) 27(-18.3,-1.27) 28(-18.3,-1.905) 29(-18.3,-2.54) 30(-18.3,-3.175) 31(-18.3,-3.81) 32(-18.3,-4.445) 33(-18.3,-5.08) 34(-18.3,-5.715) 35(-18.3,-6.35) 36(-18.3,-6.985) 37(-18.3,-7.62) 38(-18.3,-8.255) 39(-18.3,-8.89) 40(-18.3,-9.525) 41(-18.3,-10.16) 42(-18.3,-10.795) 43(-18.3,-11.43) 44(-18.3,-12.065) 45(-18.3,-12.7) 46(-18.3,-13.335) 47(-18.3,-13.97) 48(-18.3,-14.605) 49(-18.3,-15.24) 99(18.3,-15.24) 100(18.3,-14.605) 101(18.3,-13.97) 102(18.3,-13.335) 103(18.3,-12.7) 104(18.3,-12.065) 105(18.3,-11.43) 106(18.3,-10.795) 107(18.3,-10.16) 108(18.3,-9.525) 109(18.3,-8.89) 110(18.3,-8.255) 111(18.3,-7.62) 112(18.3,-6.985) 113(18.3,-6.35) 114(18.3,-5.715) 115(18.3,-5.08) 116(18.3,-4.445) 117(18.3,-3.81) 118(18.3,-3.175) 119(18.3,-2.54) 120(18.3,-1.905) 121(18.3,-1.27) 122(18.3,-0.635) 123(18.3,0) 124(18.3,0.635) 125(18.3,1.27) 126(18.3,1.905) 127(18.3,2.54) 128(18.3,3.175) 129(18.3,3.81) 130(18.3,4.445) 131(18.3,5.08) 132(18.3,5.715) 133(18.3,6.35) 134(18.3,6.985) 135(18.3,7.62) 136(18.3,8.255) 137(18.3,8.89) 138(18.3,9.525) 139(18.3,10.16) 140(18.3,10.795) 141(18.3,11.43) 142(18.3,12.065) 143(18.3,12.7) 144(18.3,13.335) 145(18.3,13.97) 146(18.3,14.605) 147(18.3,15.24)
  rect 0.35x1.8 smd: 50(-15.24,-18.3) 51(-14.605,-18.3) 52(-13.97,-18.3) 53(-13.335,-18.3) 54(-12.7,-18.3) 55(-12.065,-18.3) 56(-11.43,-18.3) 57(-10.795,-18.3) 58(-10.16,-18.3) 59(-9.525,-18.3) 60(-8.89,-18.3) 61(-8.255,-18.3) 62(-7.62,-18.3) 63(-6.985,-18.3) 64(-6.35,-18.3) 65(-5.715,-18.3) 66(-5.08,-18.3) 67(-4.445,-18.3) 68(-3.81,-18.3) 69(-3.175,-18.3) 70(-2.54,-18.3) 71(-1.905,-18.3) 72(-1.27,-18.3) 73(-0.635,-18.3) 74(0,-18.3) 75(0.635,-18.3) 76(1.27,-18.3) 77(1.905,-18.3) 78(2.54,-18.3) 79(3.175,-18.3) 80(3.81,-18.3) 81(4.445,-18.3) 82(5.08,-18.3) 83(5.715,-18.3) 84(6.35,-18.3) 85(6.985,-18.3) 86(7.62,-18.3) 87(8.255,-18.3) 88(8.89,-18.3) 89(9.525,-18.3) 90(10.16,-18.3) 91(10.795,-18.3) 92(11.43,-18.3) 93(12.065,-18.3) 94(12.7,-18.3) 95(13.335,-18.3) 96(13.97,-18.3) 97(14.605,-18.3) 98(15.24,-18.3) 148(15.24,18.3) 149(14.605,18.3) 150(13.97,18.3) 151(13.335,18.3) 152(12.7,18.3) 153(12.065,18.3) 154(11.43,18.3) 155(10.795,18.3) 156(10.16,18.3) 157(9.525,18.3) 158(8.89,18.3) 159(8.255,18.3) 160(7.62,18.3) 161(6.985,18.3) 162(6.35,18.3) 163(5.715,18.3) 164(5.08,18.3) 165(4.445,18.3) 166(3.81,18.3) 167(3.175,18.3) 168(2.54,18.3) 169(1.905,18.3) 170(1.27,18.3) 171(0.635,18.3) 172(0,18.3) 173(-0.635,18.3) 174(-1.27,18.3) 175(-1.905,18.3) 176(-2.54,18.3) 177(-3.175,18.3) 178(-3.81,18.3) 179(-4.445,18.3) 180(-5.08,18.3) 181(-5.715,18.3) 182(-6.35,18.3) 183(-6.985,18.3) 184(-7.62,18.3) 185(-8.255,18.3) 186(-8.89,18.3) 187(-9.525,18.3) 188(-10.16,18.3) 189(-10.795,18.3) 190(-11.43,18.3) 191(-12.065,18.3) 192(-12.7,18.3) 193(-13.335,18.3) 194(-13.97,18.3) 195(-14.605,18.3) 196(-15.24,18.3)
Top Overlay:
  circle w0.25: c-19.76,15.24 r0.125
  lines w0.2: -19.1,-17.397 -17.576,-16.635 ; -19.1,-17.379 -19.1,-17.651 -17.576,-19.175 -17.322,-19.175 -16.56,-17.651 ; -19.1,17.229 -19.1,17.501 -17.576,19.025 -17.322,19.025 -16.56,17.501 ; -19.1,17.247 -17.576,16.485 ; 16.56,-17.651 17.322,-19.175 17.576,-19.175 19.1,-17.651 19.1,-17.379 ; 16.56,17.501 17.322,19.025 17.576,19.025 19.1,17.501 19.1,17.229 ; 17.576,-16.635 19.1,-17.397 ; 17.576,16.485 19.1,17.247

## B-QFP-G196/T [mm] "PQFP; 196 Leads; Body 34 x 34 mm; Pitch 0.635 mm"
height 4.57
pads (196):
  rect 0.35x1.8 smd: 1(0,18.3) 2(-0.635,18.3) 3(-1.27,18.3) 4(-1.905,18.3) 5(-2.54,18.3) 6(-3.175,18.3) 7(-3.81,18.3) 8(-4.445,18.3) 9(-5.08,18.3) 10(-5.715,18.3) 11(-6.35,18.3) 12(-6.985,18.3) 13(-7.62,18.3) 14(-8.255,18.3) 15(-8.89,18.3) 16(-9.525,18.3) 17(-10.16,18.3) 18(-10.795,18.3) 19(-11.43,18.3) 20(-12.065,18.3) 21(-12.7,18.3) 22(-13.335,18.3) 23(-13.97,18.3) 24(-14.605,18.3) 25(-15.24,18.3) 75(-15.24,-18.3) 76(-14.605,-18.3) 77(-13.97,-18.3) 78(-13.335,-18.3) 79(-12.7,-18.3) 80(-12.065,-18.3) 81(-11.43,-18.3) 82(-10.795,-18.3) 83(-10.16,-18.3) 84(-9.525,-18.3) 85(-8.89,-18.3) 86(-8.255,-18.3) 87(-7.62,-18.3) 88(-6.985,-18.3) 89(-6.35,-18.3) 90(-5.715,-18.3) 91(-5.08,-18.3) 92(-4.445,-18.3) 93(-3.81,-18.3) 94(-3.175,-18.3) 95(-2.54,-18.3) 96(-1.905,-18.3) 97(-1.27,-18.3) 98(-0.635,-18.3) 99(0,-18.3) 100(0.635,-18.3) 101(1.27,-18.3) 102(1.905,-18.3) 103(2.54,-18.3) 104(3.175,-18.3) 105(3.81,-18.3) 106(4.445,-18.3) 107(5.08,-18.3) 108(5.715,-18.3) 109(6.35,-18.3) 110(6.985,-18.3) 111(7.62,-18.3) 112(8.255,-18.3) 113(8.89,-18.3) 114(9.525,-18.3) 115(10.16,-18.3) 116(10.795,-18.3) 117(11.43,-18.3) 118(12.065,-18.3) 119(12.7,-18.3) 120(13.335,-18.3) 121(13.97,-18.3) 122(14.605,-18.3) 123(15.24,-18.3) 173(15.24,18.3) 174(14.605,18.3) 175(13.97,18.3) 176(13.335,18.3) 177(12.7,18.3) 178(12.065,18.3) 179(11.43,18.3) 180(10.795,18.3) 181(10.16,18.3) 182(9.525,18.3) 183(8.89,18.3) 184(8.255,18.3) 185(7.62,18.3) 186(6.985,18.3) 187(6.35,18.3) 188(5.715,18.3) 189(5.08,18.3) 190(4.445,18.3) 191(3.81,18.3) 192(3.175,18.3) 193(2.54,18.3) 194(1.905,18.3) 195(1.27,18.3) 196(0.635,18.3)
  rect 1.8x0.35 smd: 26(-18.3,15.24) 27(-18.3,14.605) 28(-18.3,13.97) 29(-18.3,13.335) 30(-18.3,12.7) 31(-18.3,12.065) 32(-18.3,11.43) 33(-18.3,10.795) 34(-18.3,10.16) 35(-18.3,9.525) 36(-18.3,8.89) 37(-18.3,8.255) 38(-18.3,7.62) 39(-18.3,6.985) 40(-18.3,6.35) 41(-18.3,5.715) 42(-18.3,5.08) 43(-18.3,4.445) 44(-18.3,3.81) 45(-18.3,3.175) 46(-18.3,2.54) 47(-18.3,1.905) 48(-18.3,1.27) 49(-18.3,0.635) 50(-18.3,0) 51(-18.3,-0.635) 52(-18.3,-1.27) 53(-18.3,-1.905) 54(-18.3,-2.54) 55(-18.3,-3.175) 56(-18.3,-3.81) 57(-18.3,-4.445) 58(-18.3,-5.08) 59(-18.3,-5.715) 60(-18.3,-6.35) 61(-18.3,-6.985) 62(-18.3,-7.62) 63(-18.3,-8.255) 64(-18.3,-8.89) 65(-18.3,-9.525) 66(-18.3,-10.16) 67(-18.3,-10.795) 68(-18.3,-11.43) 69(-18.3,-12.065) 70(-18.3,-12.7) 71(-18.3,-13.335) 72(-18.3,-13.97) 73(-18.3,-14.605) 74(-18.3,-15.24) 124(18.3,-15.24) 125(18.3,-14.605) 126(18.3,-13.97) 127(18.3,-13.335) 128(18.3,-12.7) 129(18.3,-12.065) 130(18.3,-11.43) 131(18.3,-10.795) 132(18.3,-10.16) 133(18.3,-9.525) 134(18.3,-8.89) 135(18.3,-8.255) 136(18.3,-7.62) 137(18.3,-6.985) 138(18.3,-6.35) 139(18.3,-5.715) 140(18.3,-5.08) 141(18.3,-4.445) 142(18.3,-3.81) 143(18.3,-3.175) 144(18.3,-2.54) 145(18.3,-1.905) 146(18.3,-1.27) 147(18.3,-0.635) 148(18.3,0) 149(18.3,0.635) 150(18.3,1.27) 151(18.3,1.905) 152(18.3,2.54) 153(18.3,3.175) 154(18.3,3.81) 155(18.3,4.445) 156(18.3,5.08) 157(18.3,5.715) 158(18.3,6.35) 159(18.3,6.985) 160(18.3,7.62) 161(18.3,8.255) 162(18.3,8.89) 163(18.3,9.525) 164(18.3,10.16) 165(18.3,10.795) 166(18.3,11.43) 167(18.3,12.065) 168(18.3,12.7) 169(18.3,13.335) 170(18.3,13.97) 171(18.3,14.605) 172(18.3,15.24)
Top Overlay:
  circle w0.25: c0,19.76 r0.125
  lines w0.2: -19.1,-17.397 -17.576,-16.635 ; -19.1,-17.379 -19.1,-17.651 -17.576,-19.175 -17.322,-19.175 -16.56,-17.651 ; -19.1,17.229 -19.1,17.501 -17.576,19.025 -17.322,19.025 -16.56,17.501 ; -19.1,17.247 -17.576,16.485 ; 16.56,-17.651 17.322,-19.175 17.576,-19.175 19.1,-17.651 19.1,-17.379 ; 16.56,17.501 17.322,19.025 17.576,19.025 19.1,17.501 19.1,17.229 ; 17.576,-16.635 19.1,-17.397 ; 17.576,16.485 19.1,17.247

## B-QFP-G244/N [mm] "PQFP; 244 Leads; Body 45 x 45 mm; Pitch 0.635 mm"
height 4.57
pads (244):
  rect 1.8x0.35 smd: 1(-20.5,19.05) 2(-20.5,18.415) 3(-20.5,17.78) 4(-20.5,17.145) 5(-20.5,16.51) 6(-20.5,15.875) 7(-20.5,15.24) 8(-20.5,14.605) 9(-20.5,13.97) 10(-20.5,13.335) 11(-20.5,12.7) 12(-20.5,12.065) 13(-20.5,11.43) 14(-20.5,10.795) 15(-20.5,10.16) 16(-20.5,9.525) 17(-20.5,8.89) 18(-20.5,8.255) 19(-20.5,7.62) 20(-20.5,6.985) 21(-20.5,6.35) 22(-20.5,5.715) 23(-20.5,5.08) 24(-20.5,4.445) 25(-20.5,3.81) 26(-20.5,3.175) 27(-20.5,2.54) 28(-20.5,1.905) 29(-20.5,1.27) 30(-20.5,0.635) 31(-20.5,0) 32(-20.5,-0.635) 33(-20.5,-1.27) 34(-20.5,-1.905) 35(-20.5,-2.54) 36(-20.5,-3.175) 37(-20.5,-3.81) 38(-20.5,-4.445) 39(-20.5,-5.08) 40(-20.5,-5.715) 41(-20.5,-6.35) 42(-20.5,-6.985) 43(-20.5,-7.62) 44(-20.5,-8.255) 45(-20.5,-8.89) 46(-20.5,-9.525) 47(-20.5,-10.16) 48(-20.5,-10.795) 49(-20.5,-11.43) 50(-20.5,-12.065) 51(-20.5,-12.7) 52(-20.5,-13.335) 53(-20.5,-13.97) 54(-20.5,-14.605) 55(-20.5,-15.24) 56(-20.5,-15.875) 57(-20.5,-16.51) 58(-20.5,-17.145) 59(-20.5,-17.78) 60(-20.5,-18.415) 61(-20.5,-19.05) 123(20.5,-19.05) 124(20.5,-18.415) 125(20.5,-17.78) 126(20.5,-17.145) 127(20.5,-16.51) 128(20.5,-15.875) 129(20.5,-15.24) 130(20.5,-14.605) 131(20.5,-13.97) 132(20.5,-13.335) 133(20.5,-12.7) 134(20.5,-12.065) 135(20.5,-11.43) 136(20.5,-10.795) 137(20.5,-10.16) 138(20.5,-9.525) 139(20.5,-8.89) 140(20.5,-8.255) 141(20.5,-7.62) 142(20.5,-6.985) 143(20.5,-6.35) 144(20.5,-5.715) 145(20.5,-5.08) 146(20.5,-4.445) 147(20.5,-3.81) 148(20.5,-3.175) 149(20.5,-2.54) 150(20.5,-1.905) 151(20.5,-1.27) 152(20.5,-0.635) 153(20.5,0) 154(20.5,0.635) 155(20.5,1.27) 156(20.5,1.905) 157(20.5,2.54) 158(20.5,3.175) 159(20.5,3.81) 160(20.5,4.445) 161(20.5,5.08) 162(20.5,5.715) 163(20.5,6.35) 164(20.5,6.985) 165(20.5,7.62) 166(20.5,8.255) 167(20.5,8.89) 168(20.5,9.525) 169(20.5,10.16) 170(20.5,10.795) 171(20.5,11.43) 172(20.5,12.065) 173(20.5,12.7) 174(20.5,13.335) 175(20.5,13.97) 176(20.5,14.605) 177(20.5,15.24) 178(20.5,15.875) 179(20.5,16.51) 180(20.5,17.145) 181(20.5,17.78) 182(20.5,18.415) 183(20.5,19.05)
  rect 0.35x1.8 smd: 62(-19.05,-20.5) 63(-18.415,-20.5) 64(-17.78,-20.5) 65(-17.145,-20.5) 66(-16.51,-20.5) 67(-15.875,-20.5) 68(-15.24,-20.5) 69(-14.605,-20.5) 70(-13.97,-20.5) 71(-13.335,-20.5) 72(-12.7,-20.5) 73(-12.065,-20.5) 74(-11.43,-20.5) 75(-10.795,-20.5) 76(-10.16,-20.5) 77(-9.525,-20.5) 78(-8.89,-20.5) 79(-8.255,-20.5) 80(-7.62,-20.5) 81(-6.985,-20.5) 82(-6.35,-20.5) 83(-5.715,-20.5) 84(-5.08,-20.5) 85(-4.445,-20.5) 86(-3.81,-20.5) 87(-3.175,-20.5) 88(-2.54,-20.5) 89(-1.905,-20.5) 90(-1.27,-20.5) 91(-0.635,-20.5) 92(0,-20.5) 93(0.635,-20.5) 94(1.27,-20.5) 95(1.905,-20.5) 96(2.54,-20.5) 97(3.175,-20.5) 98(3.81,-20.5) 99(4.445,-20.5) 100(5.08,-20.5) 101(5.715,-20.5) 102(6.35,-20.5) 103(6.985,-20.5) 104(7.62,-20.5) 105(8.255,-20.5) 106(8.89,-20.5) 107(9.525,-20.5) 108(10.16,-20.5) 109(10.795,-20.5) 110(11.43,-20.5) 111(12.065,-20.5) 112(12.7,-20.5) 113(13.335,-20.5) 114(13.97,-20.5) 115(14.605,-20.5) 116(15.24,-20.5) 117(15.875,-20.5) 118(16.51,-20.5) 119(17.145,-20.5) 120(17.78,-20.5) 121(18.415,-20.5) 122(19.05,-20.5) 184(19.05,20.5) 185(18.415,20.5) 186(17.78,20.5) 187(17.145,20.5) 188(16.51,20.5) 189(15.875,20.5) 190(15.24,20.5) 191(14.605,20.5) 192(13.97,20.5) 193(13.335,20.5) 194(12.7,20.5) 195(12.065,20.5) 196(11.43,20.5) 197(10.795,20.5) 198(10.16,20.5) 199(9.525,20.5) 200(8.89,20.5) 201(8.255,20.5) 202(7.62,20.5) 203(6.985,20.5) 204(6.35,20.5) 205(5.715,20.5) 206(5.08,20.5) 207(4.445,20.5) 208(3.81,20.5) 209(3.175,20.5) 210(2.54,20.5) 211(1.905,20.5) 212(1.27,20.5) 213(0.635,20.5) 214(0,20.5) 215(-0.635,20.5) 216(-1.27,20.5) 217(-1.905,20.5) 218(-2.54,20.5) 219(-3.175,20.5) 220(-3.81,20.5) 221(-4.445,20.5) 222(-5.08,20.5) 223(-5.715,20.5) 224(-6.35,20.5) 225(-6.985,20.5) 226(-7.62,20.5) 227(-8.255,20.5) 228(-8.89,20.5) 229(-9.525,20.5) 230(-10.16,20.5) 231(-10.795,20.5) 232(-11.43,20.5) 233(-12.065,20.5) 234(-12.7,20.5) 235(-13.335,20.5) 236(-13.97,20.5) 237(-14.605,20.5) 238(-15.24,20.5) 239(-15.875,20.5) 240(-16.51,20.5) 241(-17.145,20.5) 242(-17.78,20.5) 243(-18.415,20.5) 244(-19.05,20.5)
Top Overlay:
  circle w0.25: c-21.96,19.05 r0.125
  lines w0.2: -20.828,-19.794 -22.352,-20.556 -22.352,-20.828 -20.828,-22.352 -20.574,-22.352 -19.812,-20.828 ; -20.828,19.794 -22.352,20.556 -22.352,20.828 -20.828,22.352 -20.574,22.352 -19.812,20.828 ; 19.812,-20.828 20.574,-22.352 20.828,-22.352 22.352,-20.828 22.352,-20.556 20.828,-19.794 ; 19.812,20.828 20.574,22.352 20.828,22.352 22.352,20.828 22.352,20.556 20.828,19.794

## B-QFP-G244/T [mm] "PQFP; 244 Leads; Body 45 x 45 mm; Pitch 0.635 mm"
height 4.57
pads (244):
  rect 0.35x1.8 smd: 1(0,20.5) 2(-0.635,20.5) 3(-1.27,20.5) 4(-1.905,20.5) 5(-2.54,20.5) 6(-3.175,20.5) 7(-3.81,20.5) 8(-4.445,20.5) 9(-5.08,20.5) 10(-5.715,20.5) 11(-6.35,20.5) 12(-6.985,20.5) 13(-7.62,20.5) 14(-8.255,20.5) 15(-8.89,20.5) 16(-9.525,20.5) 17(-10.16,20.5) 18(-10.795,20.5) 19(-11.43,20.5) 20(-12.065,20.5) 21(-12.7,20.5) 22(-13.335,20.5) 23(-13.97,20.5) 24(-14.605,20.5) 25(-15.24,20.5) 26(-15.875,20.5) 27(-16.51,20.5) 28(-17.145,20.5) 29(-17.78,20.5) 30(-18.415,20.5) 31(-19.05,20.5) 93(-19.05,-20.5) 94(-18.415,-20.5) 95(-17.78,-20.5) 96(-17.145,-20.5) 97(-16.51,-20.5) 98(-15.875,-20.5) 99(-15.24,-20.5) 100(-14.605,-20.5) 101(-13.97,-20.5) 102(-13.335,-20.5) 103(-12.7,-20.5) 104(-12.065,-20.5) 105(-11.43,-20.5) 106(-10.795,-20.5) 107(-10.16,-20.5) 108(-9.525,-20.5) 109(-8.89,-20.5) 110(-8.255,-20.5) 111(-7.62,-20.5) 112(-6.985,-20.5) 113(-6.35,-20.5) 114(-5.715,-20.5) 115(-5.08,-20.5) 116(-4.445,-20.5) 117(-3.81,-20.5) 118(-3.175,-20.5) 119(-2.54,-20.5) 120(-1.905,-20.5) 121(-1.27,-20.5) 122(-0.635,-20.5) 123(0,-20.5) 124(0.635,-20.5) 125(1.27,-20.5) 126(1.905,-20.5) 127(2.54,-20.5) 128(3.175,-20.5) 129(3.81,-20.5) 130(4.445,-20.5) 131(5.08,-20.5) 132(5.715,-20.5) 133(6.35,-20.5) 134(6.985,-20.5) 135(7.62,-20.5) 136(8.255,-20.5) 137(8.89,-20.5) 138(9.525,-20.5) 139(10.16,-20.5) 140(10.795,-20.5) 141(11.43,-20.5) 142(12.065,-20.5) 143(12.7,-20.5) 144(13.335,-20.5) 145(13.97,-20.5) 146(14.605,-20.5) 147(15.24,-20.5) 148(15.875,-20.5) 149(16.51,-20.5) 150(17.145,-20.5) 151(17.78,-20.5) 152(18.415,-20.5) 153(19.05,-20.5) 215(19.05,20.5) 216(18.415,20.5) 217(17.78,20.5) 218(17.145,20.5) 219(16.51,20.5) 220(15.875,20.5) 221(15.24,20.5) 222(14.605,20.5) 223(13.97,20.5) 224(13.335,20.5) 225(12.7,20.5) 226(12.065,20.5) 227(11.43,20.5) 228(10.795,20.5) 229(10.16,20.5) 230(9.525,20.5) 231(8.89,20.5) 232(8.255,20.5) 233(7.62,20.5) 234(6.985,20.5) 235(6.35,20.5) 236(5.715,20.5) 237(5.08,20.5) 238(4.445,20.5) 239(3.81,20.5) 240(3.175,20.5) 241(2.54,20.5) 242(1.905,20.5) 243(1.27,20.5) 244(0.635,20.5)
  rect 1.8x0.35 smd: 32(-20.5,19.05) 33(-20.5,18.415) 34(-20.5,17.78) 35(-20.5,17.145) 36(-20.5,16.51) 37(-20.5,15.875) 38(-20.5,15.24) 39(-20.5,14.605) 40(-20.5,13.97) 41(-20.5,13.335) 42(-20.5,12.7) 43(-20.5,12.065) 44(-20.5,11.43) 45(-20.5,10.795) 46(-20.5,10.16) 47(-20.5,9.525) 48(-20.5,8.89) 49(-20.5,8.255) 50(-20.5,7.62) 51(-20.5,6.985) 52(-20.5,6.35) 53(-20.5,5.715) 54(-20.5,5.08) 55(-20.5,4.445) 56(-20.5,3.81) 57(-20.5,3.175) 58(-20.5,2.54) 59(-20.5,1.905) 60(-20.5,1.27) 61(-20.5,0.635) 62(-20.5,0) 63(-20.5,-0.635) 64(-20.5,-1.27) 65(-20.5,-1.905) 66(-20.5,-2.54) 67(-20.5,-3.175) 68(-20.5,-3.81) 69(-20.5,-4.445) 70(-20.5,-5.08) 71(-20.5,-5.715) 72(-20.5,-6.35) 73(-20.5,-6.985) 74(-20.5,-7.62) 75(-20.5,-8.255) 76(-20.5,-8.89) 77(-20.5,-9.525) 78(-20.5,-10.16) 79(-20.5,-10.795) 80(-20.5,-11.43) 81(-20.5,-12.065) 82(-20.5,-12.7) 83(-20.5,-13.335) 84(-20.5,-13.97) 85(-20.5,-14.605) 86(-20.5,-15.24) 87(-20.5,-15.875) 88(-20.5,-16.51) 89(-20.5,-17.145) 90(-20.5,-17.78) 91(-20.5,-18.415) 92(-20.5,-19.05) 154(20.5,-19.05) 155(20.5,-18.415) 156(20.5,-17.78) 157(20.5,-17.145) 158(20.5,-16.51) 159(20.5,-15.875) 160(20.5,-15.24) 161(20.5,-14.605) 162(20.5,-13.97) 163(20.5,-13.335) 164(20.5,-12.7) 165(20.5,-12.065) 166(20.5,-11.43) 167(20.5,-10.795) 168(20.5,-10.16) 169(20.5,-9.525) 170(20.5,-8.89) 171(20.5,-8.255) 172(20.5,-7.62) 173(20.5,-6.985) 174(20.5,-6.35) 175(20.5,-5.715) 176(20.5,-5.08) 177(20.5,-4.445) 178(20.5,-3.81) 179(20.5,-3.175) 180(20.5,-2.54) 181(20.5,-1.905) 182(20.5,-1.27) 183(20.5,-0.635) 184(20.5,0) 185(20.5,0.635) 186(20.5,1.27) 187(20.5,1.905) 188(20.5,2.54) 189(20.5,3.175) 190(20.5,3.81) 191(20.5,4.445) 192(20.5,5.08) 193(20.5,5.715) 194(20.5,6.35) 195(20.5,6.985) 196(20.5,7.62) 197(20.5,8.255) 198(20.5,8.89) 199(20.5,9.525) 200(20.5,10.16) 201(20.5,10.795) 202(20.5,11.43) 203(20.5,12.065) 204(20.5,12.7) 205(20.5,13.335) 206(20.5,13.97) 207(20.5,14.605) 208(20.5,15.24) 209(20.5,15.875) 210(20.5,16.51) 211(20.5,17.145) 212(20.5,17.78) 213(20.5,18.415) 214(20.5,19.05)
Top Overlay:
  circle w0.25: c0,21.96 r0.125
  lines w0.2: -22.252,20.696 -20.728,22.22 -20.465,22.226 -19.703,20.702 ; -22.247,20.431 -20.723,19.669 ; -22.24,20.433 -22.24,20.705 ; -20.658,-19.592 -22.182,-20.354 -22.182,-20.626 -20.658,-22.15 -20.404,-22.15 -19.642,-20.626 ; 19.6,-20.636 20.362,-22.16 20.616,-22.16 22.14,-20.636 22.14,-20.364 20.616,-19.602 ; 19.667,20.635 20.429,22.159 20.683,22.159 22.207,20.635 22.207,20.363 20.683,19.601

## BANANA_TRIPLE [mil] "Triple Banana jack, panel mount style"
height 318.9
pads (3):
  round 440 hole 280: 1(-750,0) 2(0,0) 3(750,0)
via 0,200 diameter 56 hole 28
via -141.42,141.42 diameter 56 hole 28
via -200,0 diameter 56 hole 28
via -141.42,-141.42 diameter 56 hole 28
via 0,-200 diameter 56 hole 28
via 141.42,-141.42 diameter 56 hole 28
via 200,0 diameter 56 hole 28
via 141.42,141.42 diameter 56 hole 28
via -608.58,141.42 diameter 56 hole 28
via -550,0 diameter 56 hole 28
via -608.58,-141.42 diameter 56 hole 28
via -750,-200 diameter 56 hole 28
via -891.42,-141.42 diameter 56 hole 28
via -950,0 diameter 56 hole 28
via -891.42,141.42 diameter 56 hole 28
via -750,200 diameter 56 hole 28
via 891.42,141.42 diameter 56 hole 28
via 950,0 diameter 56 hole 28
via 891.42,-141.42 diameter 56 hole 28
via 750,-200 diameter 56 hole 28
via 608.58,-141.42 diameter 56 hole 28
via 550,0 diameter 56 hole 28
via 608.58,141.42 diameter 56 hole 28
via 750,200 diameter 56 hole 28
Mechanical 13:
  circle w5: c-750,0 r250
  circle w5: c-750,0 r225
  circle w5: c0,0 r225
  circle w5: c0,0 r83
  circle w5: c-750,0 r83
  circle w5: c0,0 r250
  circle w5: c750,0 r225
  circle w5: c750,0 r83
  circle w5: c750,0 r250
  lines w5: -750,-315 cw(c-750,0) -750,315 ; -750,-315 -750,-283.94 ; -750,-315 750,-315 ; -750,-283.94 cw(c-750,0) -750,283.94 ; -750,-283.94 750,-283.94 ; -750,283.94 750,283.94 ; -750,283.94 -750,315 ; -750,315 750,315 ; 750,-315 ccw(c750,0) 750,315 ; 750,-315 750,-283.94 ; 750,-283.94 ccw(c750,0) 750,283.94 ; 750,283.94 750,315 ; -750,-308.9 cw(c-750,0) -750,308.9 750,308.9 cw(c750,0) 750,-308.9 -750,-308.9
3D body: height 380, standoff -840, extent -1064.99,-314.99 1065,315

## BAT-2 [mm] "Battery; 2 Leads"
pads (2):
  oval 5.588x3.302 hole 2.75: 1(-6.5,0) 2(6.5,0)
Top Overlay:
  lines w0.2: -15,2 15,2
  lines w0.254: -15,2 -15,-56 15,-56 15,2
  text "+" at -11,0 h1.15
3D body: height 47.94, standoff -21.71, extent -31.836,-66.153 31.794,16.267

## BAT_Holder [mm] "Battery; 2 Leads"
pads (2):
  oval 5.588x3.302 hole 2.75: 1(-6.5,0) 2(6.5,0)
Top Overlay:
  lines w0.2: -15,2.794 15,2.794
  lines w0.254: -15,2.794 -15,-56 15,-56 15,2.794
  text "+" at -10.795,3.048 h1.15
3D body: height 23.26, standoff -2.03, extent -15.36,-53.02 14.61,1.97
